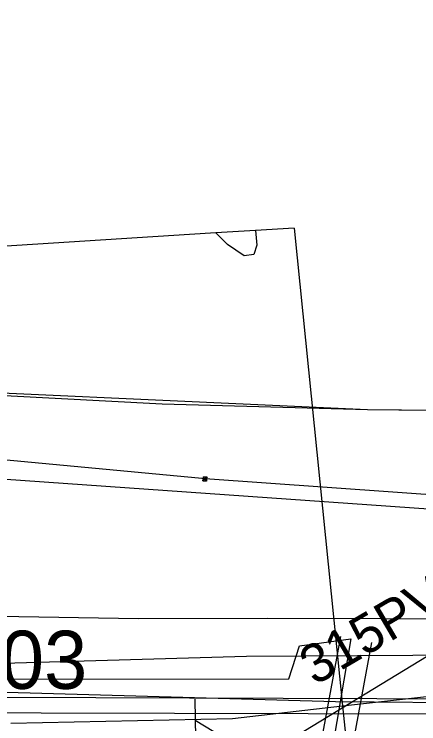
# Model space of a CAD drawing. Extents: x -746464 to -745690, y -1051581 to -1049993.
# Drawn here: x -745960.14 to -745949.7, y -1051030.2 to -1051011.89 of the extents above; entities that cross this region are included whole.
import ezdxf

# ---------------------------------------------------------------- set-up
doc = ezdxf.new("R2010")
doc.units = 0
for name, color, linetype in [('04_CETIN_neprovozovane', 7, 'Continuous'), ('04_CETIN_NN', 7, 'Continuous'), ('04_CETIN_sdelovaci_podzem', 7, 'Continuous'), ('45_Eltodo_chranicka', 7, 'Continuous'), ('45_Eltodo_popisy', 7, 'Continuous'), ('45_Eltodo_sdelovaci_kabel_ovladaci', 7, 'Continuous'), ('45_Eltodo_vedeni_NN_zemni', 7, 'Continuous'), ('51_PVaK_kanal_jednotna_overena poloha_rad', 7, 'Continuous'), ('51_PVaK_kanal_objekty', 7, 'Continuous'), ('51_PVaK_kanal_popisy', 7, 'Continuous'), ('51_PVaK_vodovod_chranicky_objekty', 7, 'Continuous'), ('51_PVaK_vodovod_overena poloha_rad', 7, 'Continuous'), ('51_PVaK_vodovod_zruseno_overena poloha', 7, 'Continuous'), ('55_PREdi_NN', 7, 'Continuous')]:
    doc.layers.add(name, color=color, linetype=linetype)

msp = doc.modelspace()

# ---------------------------------------------------------------- linework, layer by layer
at = {"layer": '04_CETIN_neprovozovane'}
for points in [[(-745953.92, -1051017.47), (-745953.88, -1051017.85), (-745953.96, -1051018.09), (-745954.21, -1051018.12), (-745954.64, -1051017.83), (-745954.94, -1051017.53)], [(-745952.92, -1051017.41), (-745951.67, -1051029.74)], [(-745951.67, -1051029.74), (-745945.33, -1051029.03)], [(-745954.51, -1051030.06), (-745951.67, -1051029.74)], [(-745951.67, -1051029.74), (-745951.55, -1051030.89), (-745951.98, -1051040.88), (-745951.99, -1051041.18), (-745945.4, -1051041.47)], [(-745960.23, -1051030.18), (-745954.51, -1051030.06)]]:
    msp.add_lwpolyline(points, dxfattribs=at)
at = {"layer": '04_CETIN_NN'}
msp.add_lwpolyline([(-745933.08, -1051029.24), (-745939.9, -1051029.74), (-745951.85, -1051029.63), (-745972.78, -1051029.04), (-745990.44, -1051029.07)], dxfattribs=at)
at = {"layer": '04_CETIN_sdelovaci_podzem'}
for points in [[(-745954.94, -1051017.53), (-745955.62, -1051017.57), (-745980.07, -1051019.13), (-745981.49, -1051019.58), (-745982.89, -1051019.53)], [(-745953.92, -1051017.47), (-745954.94, -1051017.53)], [(-745952.92, -1051017.41), (-745953.92, -1051017.47)], [(-745933.08, -1051029.24), (-745939.9, -1051029.74), (-745951.85, -1051029.63), (-745972.78, -1051029.04), (-745990.44, -1051029.07)], [(-745933.08, -1051029.24), (-745939.9, -1051029.74), (-745951.85, -1051029.63)]]:
    msp.add_lwpolyline(points, dxfattribs=at)
at = {"layer": '45_Eltodo_chranicka'}
for points in [[(-745951.722, -1051027.95), (-745953.954, -1051040.012)], [(-745950.92, -1051028.098), (-745953.152, -1051040.16)]]:
    msp.add_lwpolyline(points, dxfattribs=at)
at = {"layer": '45_Eltodo_sdelovaci_kabel_ovladaci'}
for points in [[(-746165.45, -1051019.12), (-746164.645, -1051018.484), (-746163.012, -1051015.524), (-746155.55, -1051020.103), (-746128.916, -1051021.082), (-746094.892, -1051022.957), (-746062.41, -1051024.051), (-746028.782, -1051025.923), (-745993.864, -1051027.813), (-745962.878, -1051029.504), (-745938.694, -1051029.59), (-745937.853, -1051017.666)], [(-746165.45, -1051019.12), (-746164.312, -1051018.623), (-746162.86, -1051016.086), (-746155.668, -1051020.501), (-746128.943, -1051021.481), (-746094.909, -1051023.356), (-746062.428, -1051024.45), (-746028.804, -1051026.323), (-745993.885, -1051028.213), (-745962.902, -1051029.904), (-745931.905, -1051029.989), (-745932.65, -1051042.244), (-745896.705, -1051050.601), (-745888.091, -1051054.568), (-745887.715, -1051053.926), (-745888.006, -1051054.643), (-745887.529, -1051054.877), (-745867.231, -1051055.559), (-745868.29, -1051094.52)]]:
    msp.add_lwpolyline(points, dxfattribs=at)
at = {"layer": '45_Eltodo_vedeni_NN_zemni'}
for points in [[(-746165.45, -1051019.12), (-746165.385, -1051018.211), (-746163.315, -1051014.399), (-746155.315, -1051019.309), (-746128.86, -1051020.284), (-746094.856, -1051022.157), (-746062.375, -1051023.251), (-746028.738, -1051025.124), (-745993.82, -1051027.014), (-745962.83, -1051028.706), (-745954.147, -1051028.453), (-745931.268, -1051028.32), (-745933.203, -1051055.903)], [(-746165.45, -1051019.12), (-746164.568, -1051017.613), (-746163.161, -1051014.992), (-746155.446, -1051019.718), (-746128.935, -1051020.682), (-746094.904, -1051022.556), (-746062.441, -1051023.642), (-746028.749, -1051025.516), (-745993.88, -1051027.407), (-745962.99, -1051029.049), (-745953.059, -1051029.043), (-745952.784, -1051028.189)], [(-745961.284, -1051029.123), (-745960.552, -1051027.423), (-745956.934, -1051027.485), (-745953.601, -1051027.472), (-745938.954, -1051027.514), (-745938.2, -1051017.633), (-745937.853, -1051017.666)], [(-745952.781, -1051028.189), (-745951.46, -1051028.005), (-745953.535, -1051040.299), (-745960.06, -1051040.379)]]:
    msp.add_lwpolyline(points, dxfattribs=at)
at = {"layer": '51_PVaK_kanal_jednotna_overena poloha_rad'}
msp.add_line((-745946.46, -1051026.61), (-745952.87, -1051030.52), dxfattribs=at)
at = {"layer": '51_PVaK_kanal_objekty'}
msp.add_lwpolyline([(-745955.485, -1051029.568), (-745955.467, -1051030.568), (-745954.753, -1051030.555), (-745955.475, -1051030.117)], dxfattribs=at)
at = {"layer": '51_PVaK_vodovod_chranicky_objekty'}
for p, q in [((-745955.168, -1051023.835), (-745955.274, -1051023.927)), ((-745955.274, -1051023.927), (-745955.273, -1051023.907)), ((-745955.274, -1051023.927), (-745955.254, -1051023.929)), ((-745955.267, -1051023.828), (-745955.269, -1051023.848)), ((-745955.175, -1051023.934), (-745955.267, -1051023.828)), ((-745955.267, -1051023.828), (-745955.247, -1051023.829)), ((-745955.175, -1051023.934), (-745955.195, -1051023.933)), ((-745955.168, -1051023.835), (-745955.188, -1051023.833)), ((-745955.175, -1051023.934), (-745955.173, -1051023.914)), ((-745955.168, -1051023.835), (-745955.169, -1051023.854))]:
    msp.add_line(p, q, dxfattribs=at)
msp.add_lwpolyline([(-745955.271, -1051023.877), (-745955.271, -1051023.882), (-745955.271, -1051023.887), (-745955.27, -1051023.893), (-745955.268, -1051023.898), (-745955.266, -1051023.903), (-745955.263, -1051023.907), (-745955.26, -1051023.911), (-745955.257, -1051023.916), (-745955.253, -1051023.919), (-745955.249, -1051023.922), (-745955.244, -1051023.925), (-745955.239, -1051023.928), (-745955.234, -1051023.929), (-745955.23, -1051023.93), (-745955.225, -1051023.931), (-745955.22, -1051023.931), (-745955.215, -1051023.931), (-745955.209, -1051023.93), (-745955.204, -1051023.928), (-745955.199, -1051023.926), (-745955.195, -1051023.923), (-745955.191, -1051023.92), (-745955.186, -1051023.916), (-745955.183, -1051023.913), (-745955.18, -1051023.909), (-745955.177, -1051023.904), (-745955.174, -1051023.899), (-745955.173, -1051023.894), (-745955.172, -1051023.889), (-745955.171, -1051023.884), (-745955.171, -1051023.879), (-745955.171, -1051023.874), (-745955.172, -1051023.869), (-745955.174, -1051023.864), (-745955.176, -1051023.859), (-745955.179, -1051023.855), (-745955.182, -1051023.851), (-745955.186, -1051023.846), (-745955.189, -1051023.843), (-745955.193, -1051023.84), (-745955.198, -1051023.836), (-745955.203, -1051023.834), (-745955.208, -1051023.833), (-745955.213, -1051023.831), (-745955.218, -1051023.831), (-745955.223, -1051023.831), (-745955.228, -1051023.831), (-745955.233, -1051023.832), (-745955.238, -1051023.834), (-745955.243, -1051023.836), (-745955.247, -1051023.839), (-745955.251, -1051023.842), (-745955.256, -1051023.845), (-745955.259, -1051023.849), (-745955.262, -1051023.853), (-745955.266, -1051023.858), (-745955.268, -1051023.863), (-745955.269, -1051023.868), (-745955.271, -1051023.872), (-745955.271, -1051023.877)], dxfattribs=at)
at = {"layer": '51_PVaK_vodovod_overena poloha_rad'}
msp.add_lwpolyline([(-745946.44, -1051024.52), (-745946.61, -1051024.51), (-745946.8, -1051024.5), (-745948.71, -1051024.35), (-745948.8, -1051024.33), (-745955.22, -1051023.88), (-745955.39, -1051023.86), (-745964.47, -1051023.01), (-745981.09, -1051022.1), (-745999.23, -1051021.07), (-745999.38, -1051021.06), (-745999.58, -1051021.03), (-745999.84, -1051021.01)], dxfattribs=at)
at = {"layer": '51_PVaK_vodovod_zruseno_overena poloha'}
msp.add_lwpolyline([(-745946.756, -1051024.848), (-745999.298, -1051021.156), (-746000.52, -1051021.07)], dxfattribs=at)
at = {"layer": '55_PREdi_NN'}
for points in [[(-745994.018, -1051019.111), (-745994.063, -1051020.123), (-745951.022, -1051022.089), (-745933.461, -1051022.259), (-745932.788, -1050993.628), (-745930.263, -1050978.766), (-745925.944, -1050974.322)], [(-746029.221, -1050989.851), (-746029.798, -1050992.984), (-746030.146, -1050994.872), (-746030.876, -1050998.845), (-746031.74, -1051003.504), (-746033.533, -1051012.556), (-746034.422, -1051016.706), (-746033.363, -1051018.26), (-746030.431, -1051018.367), (-745978.926, -1051020.881), (-745968.352, -1051021.304), (-745956.326, -1051021.94), (-745951.022, -1051022.089), (-745932.338, -1051022.282)]]:
    msp.add_lwpolyline(points, dxfattribs=at)

# ---------------------------------------------------------------- texts
at = {"layer": '45_Eltodo_popisy'}
msp.add_text('515803', height=1.5, dxfattribs=at).set_placement((-745964.952, -1051029.298))
at = {"layer": '51_PVaK_kanal_popisy'}
msp.add_text('315PVC', height=1, rotation=30.3828, dxfattribs=at).set_placement((-745952.386, -1051029.227))

doc.saveas('drawing.dxf')
